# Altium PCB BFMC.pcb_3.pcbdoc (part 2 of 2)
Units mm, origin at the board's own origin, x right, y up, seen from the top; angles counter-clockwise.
Board outline 133.24 x 103.12 mm, 2 copper layers (Top Layer, Bottom Layer); 130 components, 62 nets, 361 pads, 103 vias.
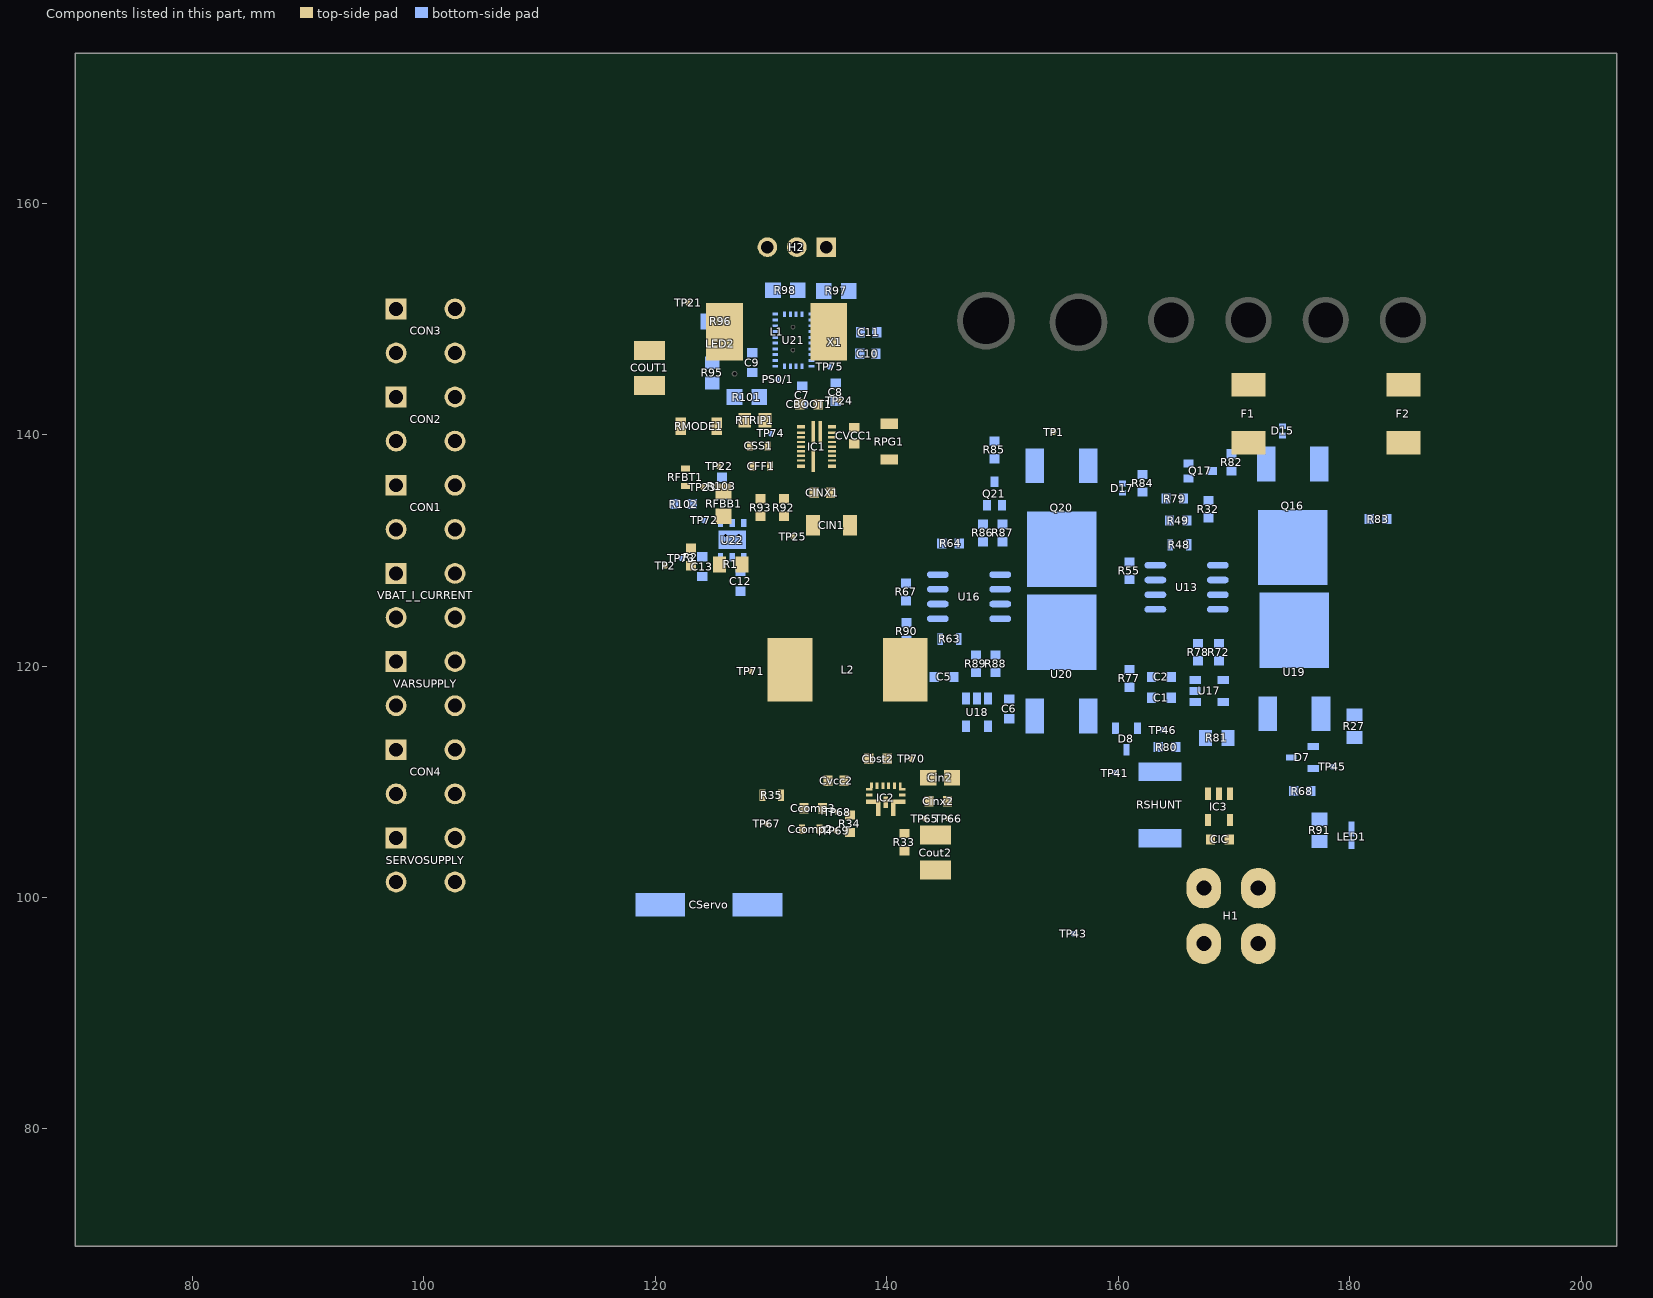
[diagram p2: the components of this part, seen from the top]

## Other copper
Top Layer:
  region net ISHUNT: 170.514,109.198 170.514,108.698 ccw(c170.514,107.877) 169.912,108.435 169.912,109.505 ccw(c170.514,109.941)
  region net UBATT: 166.73,108.725 166.73,109.225 ccw(c166.73,110.37) 167.48,109.505 167.48,108.435 ccw(c166.73,107.61)
  region net OUT_BATT: 166.73,106.445 166.73,106.945 ccw(c166.73,108.06) 167.48,107.235 167.48,106.165 ccw(c166.73,105.3)
  region net +5V: 169.896,105.415 169.396,105.415 ccw(c151.798,105.415) 169.38,106.165 169.912,106.165 ccw(c187.494,105.415)
  region net ADC1: 120.437,128.405 120.674,128.905 120.849,128.912 120.612,128.604 120.609,128.611 120.603,128.611 120.587,128.596 120.541,128.525 120.486,128.444 120.46,128.416 120.448,128.408
  region net ADC1: 121.037,128.905 121.274,128.405 121.263,128.408 121.251,128.416 121.225,128.444 121.17,128.525 121.124,128.596 121.108,128.611 121.102,128.611 121.099,128.604 120.862,128.912
  region net VOUT1: 140.707,106.797 140.407,106.797 ccw(c139.843,106.797) 140.357,107.029 140.757,107.029 ccw(c141.27,106.797)
  region: 139.384,106.648 139.13,106.648 ccw(c138.099,106.648) 139.057,107.029 139.457,107.029 ccw(c140.414,106.648)
  region net +5V: 141.482,108.854 141.182,108.854 ccw(c140.636,108.854) 141.032,109.229 141.607,109.229 ccw(c142.105,108.854)
  region net +5V: 141.182,109.342 141.482,109.342 ccw(c142.071,109.342) 141.607,108.979 141.057,108.979 ccw(c140.592,109.342)
  region net VOUT1: 141.973,108.406 141.973,108.152 ccw(c141.973,107.198) 141.607,108.079 141.607,108.479 ccw(c141.973,109.36)
  region net SW_1: 139.757,108.979 140.057,108.979 ccw(c140.707,108.979) 140.107,108.729 139.707,108.729 ccw(c139.107,108.979)
  region: 138.11,108.152 138.11,108.406 ccw(c138.11,108.506) 138.207,108.479 138.207,108.079 ccw(c138.11,108.052)
  region: 139.152,108.86 139.406,108.86 ccw(c140.88,108.86) 139.457,108.479 138.962,108.479 ccw(c138.676,108.86)
  region net FB_1: 137.756,109.229 137.756,109.529 ccw(c138.206,111.529) 138.206,109.479 138.206,109.229
  region net FB_1: 129.864,106.15 129.364,105.969 129.367,105.981 129.374,105.993 129.398,106.019 129.469,106.07 129.504,106.093 129.53,106.114 129.541,106.131 129.539,106.138 129.532,106.144 129.883,106.325 129.87,106.238
  region net COMP: 135.373,107.5 135.581,107.717 135.615,107.682 135.649,107.651 135.686,107.629 135.707,107.623 135.731,107.62 135.472,107.352 135.468,107.375 135.461,107.397 135.439,107.433 135.408,107.466
  region net COMP: 136.059,107.238 135.847,107.026 135.815,107.059 135.782,107.089 135.746,107.11 135.726,107.117 135.703,107.121 135.971,107.38 135.98,107.338 136,107.302 136.028,107.27
  region net $3N2936: 136.02,105.776 135.963,105.476 135.907,105.478 135.863,105.485 135.795,105.505 135.764,105.514 135.728,105.521 135.684,105.523 135.629,105.52 135.845,105.813 135.854,105.788 135.867,105.772 135.885,105.765 135.907,105.763 135.96,105.77
  region net $3N2936: 135.178,105.765 135.323,106.065 135.366,106.063 135.399,106.056 135.45,106.036 135.474,106.027 135.501,106.019 135.534,106.015 135.576,106.017 135.353,105.728 135.345,105.753 135.332,105.769 135.314,105.776 135.292,105.778 135.239,105.771
  region net OUT_BATT: 133.475,139.113 133.775,139.113 133.775,138.663 133.475,138.663
  region: 135.425,139.763 135.125,139.763 ccw(c134.8,139.763) 134.925,140.063 135.625,140.063 ccw(c135.75,139.763)
  region: 135.425,139.363 135.125,139.363 ccw(c134.8,139.363) 134.925,139.663 135.625,139.663 ccw(c135.75,139.363)
  region: 135.125,140.163 135.425,140.163 ccw(c135.75,140.163) 135.625,139.863 134.925,139.863 ccw(c134.8,140.163)
  region: 135.425,138.963 135.125,138.963 ccw(c134.8,138.963) 134.925,139.263 135.625,139.263 ccw(c135.75,138.963)
  region: 135.125,139.763 135.425,139.763 ccw(c135.75,139.763) 135.625,139.463 134.925,139.463 ccw(c134.8,139.763)
  region: 135.425,138.563 135.125,138.563 ccw(c134.8,138.563) 134.925,138.863 135.625,138.863 ccw(c135.75,138.563)
  region: 135.125,139.363 135.425,139.363 ccw(c135.75,139.363) 135.625,139.063 134.925,139.063 ccw(c134.8,139.363)
  region: 135.425,138.163 135.125,138.163 ccw(c134.8,138.163) 134.925,138.463 135.625,138.463 ccw(c135.75,138.163)
  region: 135.125,138.963 135.425,138.963 ccw(c135.75,138.963) 135.625,138.663 134.925,138.663 ccw(c134.8,138.963)
  region: 135.425,137.763 135.125,137.763 ccw(c134.8,137.763) 134.925,138.063 135.625,138.063 ccw(c135.75,137.763)
  region: 135.125,138.563 135.425,138.563 ccw(c135.75,138.563) 135.625,138.263 134.925,138.263 ccw(c134.8,138.563)
  region: 135.425,137.263 135.125,137.263 ccw(c134.625,137.263) 134.925,137.663 135.625,137.663 ccw(c135.925,137.263)
  region: 135.125,138.163 135.425,138.163 ccw(c135.75,138.163) 135.625,137.863 134.925,137.863 ccw(c134.8,138.163)
  region: 136.006,137.39 136.006,137.136 ccw(c136.006,133.969) 135.625,137.113 135.625,137.413 ccw(c136.006,140.557)
  region: 135.125,137.763 135.425,137.763 ccw(c135.831,137.763) 135.625,137.413 134.925,137.413 ccw(c134.718,137.763)
  region net SW: 134.098,141.544 134.352,141.544 ccw(c137.519,141.544) 134.375,141.163 134.075,141.163 ccw(c130.93,141.544)
  region net FB: 124.424,135.569 124.424,135.369 124.376,135.361 124.331,135.342 124.288,135.314 124.249,135.283 124.249,135.655 124.288,135.624 124.331,135.596 124.376,135.576
  region net FB: 123.741,135.369 123.741,135.569 123.789,135.576 123.835,135.596 123.877,135.624 123.916,135.655 123.916,135.283 123.877,135.314 123.835,135.342 123.789,135.361
  region net EN: 130.287,134.326 130.287,134.58 ccw(c130.287,135.057) 130.668,134.771 130.668,134.136 ccw(c130.287,133.85)
  region net EN: 129,135 129.2,135 ccw(c129.35,135.007) 129.35,134.857 128.85,134.857 ccw(c128.85,135.007)
  region net EN: 129.913,134.58 129.913,134.326 ccw(c129.913,133.85) 129.532,134.136 129.532,134.771 ccw(c129.913,135.057)
  region net +5V: 142.484,110.227 142.484,110.481 ccw(c142.484,110.957) 142.865,110.672 142.865,110.037 ccw(c142.484,109.751)
  region net VCCBOOST: 137.156,110.229 137.156,109.929 ccw(c137.156,109.367) 136.706,109.704 136.706,110.454 ccw(c137.156,110.792)
  region net VOUT1: 146.125,105.896 146.125,104.896 ccw(c146.125,104.228) 145.557,104.579 145.557,106.214 ccw(c146.125,106.564)
  region net VOUT1: 141.357,106.078 141.657,106.078 ccw(c141.882,106.184) 141.882,105.936 141.132,105.936 ccw(c141.132,106.184)
  region net FB_1: 140.325,103.776 140.325,104.276 ccw(c140.325,106.188) 141.075,104.429 141.075,103.622 ccw(c140.325,101.864)
  region net COMP: 135.953,106.982 135.953,107.282 ccw(c135.953,107.789) 136.375,107.507 136.375,106.757 ccw(c135.953,106.475)
  region net COMP: 136.724,107.917 136.978,107.917 ccw(c137.454,107.917) 137.168,107.536 136.533,107.536 ccw(c136.247,107.917)
  region net $3N2936: 135.925,105.476 135.925,105.776 ccw(c135.925,106.338) 136.375,106.001 136.375,105.251 ccw(c135.925,104.913)
  region net VCC: 136.3,140.513 136.3,140.813 ccw(c136.3,141.448) 136.75,141 136.75,140.288 ccw(c136.3,139.95)
  region net VCC: 138.143,140.85 138.143,140.35 ccw(c138.143,139.464) 137.65,140.2 137.65,141 ccw(c138.143,141.736)
  region net OUT_BATT: 133.475,135.861 133.775,135.861 ccw(c134.337,135.861) 134,135.411 133.332,135.411 ccw(c132.691,135.861)
  region net OUT_BATT: 128.786,129.035 128.786,128.535 ccw(c128.786,127.597) 128.036,128.16 128.036,129.41 ccw(c128.786,129.972)
  region net ADC1: 124.221,128.405 124.221,128.905 ccw(c124.221,129.843) 124.971,129.28 124.971,128.096 ccw(c124.221,127.34)
  region net +5V: 169.396,106.215 169.896,106.215 ccw(c173.449,106.215) 169.976,105.465 169.176,105.465 ccw(c168.007,106.215)
  region net +5V: 169.906,103.815 169.406,103.815 ccw(c168.068,103.815) 169.176,104.565 169.976,104.565 ccw(c173.957,103.815)
  region net BST: 140.574,112.02 140.567,111.668 ccw(c140.553,111.555) 140.439,111.555 140.439,112.424 ccw(c141.112,112.424)
  region net SW_1: 137.589,111.855 137.589,112.155 ccw(c137.589,112.718) 138.039,112.38 138.039,111.63 ccw(c137.589,111.293)
  region net SW_1: 138.631,111.174 138.377,111.174 ccw(c137.901,111.174) 138.187,111.555 138.822,111.555 ccw(c139.107,111.174)
  region net COMP: 135.286,107.829 135.286,107.529 ccw(c135.286,106.966) 134.836,107.304 134.836,108.054 ccw(c135.286,108.391)
  region net BOOT: 131.736,142.425 131.736,142.725 ccw(c131.736,143.094) 132.076,142.95 132.076,142.2 ccw(c131.736,142.056)
  region net FB: 123.3,135.569 123.3,135.369 ccw(c123.3,134.483) 123,135.317 123,135.719 ccw(c123.3,135.944)
  region net FB: 126.888,135.2 126.888,135 ccw(c126.888,134.625) 126.588,134.85 126.588,135.35 ccw(c126.888,135.575)
  region net FB: 124.911,135.369 124.911,135.569 ccw(c124.911,135.944) 125.211,135.719 125.211,135.219 ccw(c124.911,134.994)
  region net MODE: 126.056,140.815 126.056,140.615 ccw(c126.056,140.24) 125.756,140.465 125.756,140.965 ccw(c126.056,141.19)
  region net PGOOD: 140.35,136.95 140.05,136.95 ccw(c139.487,136.95) 139.825,137.4 140.575,137.4 ccw(c140.912,136.95)
  region net VCC: 138.7,140.838 138.7,141.338 ccw(c138.7,145.921) 139.45,141.4 139.45,140.5 ccw(c138.7,139.837)
  region net TRIP: 130.207,141.349 130.207,141.149 ccw(c130.207,140.965) 130.026,140.999 130.026,141.499 ccw(c130.207,141.533)
  region net FB: 130.441,137.364 130.441,137.164 ccw(c130.441,136.789) 130.141,137.014 130.141,137.514 ccw(c130.441,137.739)
  region net FB: 129.991,136.564 129.791,136.564 ccw(c129.416,136.564) 129.641,136.864 130.141,136.864 ccw(c130.366,136.564)
  region net SS_REFIN: 130.236,139.063 130.236,138.863 ccw(c130.236,138.488) 129.936,138.713 129.936,139.213 ccw(c130.236,139.438)
  region net $3N2936: 134.877,106.065 134.877,105.765 ccw(c134.877,105.203) 134.427,105.54 134.427,106.29 ccw(c134.877,106.628)
  region net FB_1: 131.556,109.005 131.556,108.705 ccw(c131.556,108.143) 131.106,108.48 131.106,109.23 ccw(c131.556,109.568)
  region net VBATT1: 165.656,97.399 165.905,97.857 165.992,97.776 166.085,97.703 166.184,97.641 166.234,97.614 166.286,97.592 166.338,97.574 166.391,97.56 166.444,97.552 166.497,97.549 166.551,97.551 166.604,97.561 166.657,97.577 166.709,97.6 165.936,96.618 165.945,96.667 165.949,96.718 165.949,96.77 165.945,96.823 165.924,96.929 165.89,97.035 165.844,97.137 165.788,97.234 165.725,97.322
  region net OUT_BATT2: 171.694,103.383 172.494,103.383 172.497,103.306 172.507,103.227 172.523,103.146 172.545,103.063 172.572,102.98 172.604,102.897 172.641,102.814 172.681,102.733 172.772,102.574 172.873,102.427 172.927,102.359 172.982,102.295 173.037,102.236 173.094,102.183 171.094,102.183 171.15,102.236 171.205,102.295 171.26,102.359 171.314,102.427 171.415,102.574 171.506,102.733 171.546,102.814 171.583,102.897 171.615,102.98 171.642,103.063 171.664,103.146 171.68,103.227 171.69,103.306
  region: 131.047,138.513 131.189,138.372 131.16,138.333 131.142,138.286 131.131,138.237 131.126,138.187 130.863,138.451 130.912,138.455 130.962,138.466 131.008,138.485
  region: 131.28,140.935 131.054,140.878 130.962,140.964 130.912,141.006 130.863,141.042 131.219,141.121 131.208,141.097 131.204,141.072 131.207,141.048 131.214,141.024 131.242,140.977
  region net PGOOD: 131.743,136.636 132.043,136.647 132.042,136.598 132.045,136.552 132.056,136.51 132.066,136.491 132.081,136.472 131.709,136.461 131.723,136.481 131.732,136.501 131.742,136.543 131.743,136.588
  region net PGOOD: 139.735,136.648 139.947,136.435 139.912,136.401 139.882,136.368 139.859,136.331 139.852,136.31 139.849,136.286 139.586,136.55 139.609,136.553 139.631,136.56 139.668,136.582 139.701,136.613
  region net +5V: 142.027,109.592 ccw(c141.205,109.592) 141.727,110.227 142.177,110.354 142.627,110.227 ccw(c143.149,109.592) 142.327,109.592
Bottom Layer:
  region net $1N1798: 177.715,113.3 177.715,112.8 ccw(c177.715,111.388) 177.325,112.745 177.325,113.355 ccw(c177.715,114.712)
  region net $1N1798: 176.587,113.636 177.087,113.636 ccw(c177.372,113.636) 177.325,113.355 176.349,113.355 ccw(c176.301,113.636)
  region net UBATT: 173.725,111.85 173.725,112.35 ccw(c173.725,137.1) 174.475,112.361 174.475,111.839 ccw(c173.725,87.1)
  region net $1N1788: 159.45,115.401 160.05,115.401 ccw(c167.811,115.401) 160.055,115.125 159.445,115.125 ccw(c151.688,115.401)
  region net $1N1788: 159.95,113.841 159.55,113.841 ccw(c159.045,113.841) 159.445,114.15 160.055,114.15 ccw(c160.455,113.841)
  region net UBATT: 160.95,111.525 160.45,111.525 ccw(c135.7,111.525) 160.438,112.275 160.961,112.275 ccw(c185.7,111.525)
  region net UBATT: 161.711,113.013 161.711,112.513 ccw(c161.711,111.21) 160.961,112.275 160.961,113.25 ccw(c161.711,114.315)
  region net $1N2516: 166.314,135.544 165.814,135.544 ccw(c165.48,135.544) 165.614,135.85 166.514,135.85 ccw(c166.647,135.544)
  region net $1N2412: 169.296,137.11 169.296,136.61 ccw(c169.296,133.747) 168.546,136.51 168.546,137.21 ccw(c169.296,139.972)
  region net $1N20962: 166.88,132.81 166.88,132.31 ccw(c166.88,131.408) 166.336,132.128 166.336,132.992 ccw(c166.88,133.712)
  region net $1N20946: 164.576,131.893 164.276,131.893 ccw(c164.042,131.893) 164.051,132.128 164.801,132.128 ccw(c164.811,131.893)
  region net $1N20674: 161.206,126.328 160.706,126.328 ccw(c159.07,126.328) 160.524,127.078 161.388,127.078 ccw(c162.842,126.328)
  region net $1N20674: 162.138,127.685 162.138,127.185 ccw(c162.138,124.49) 161.388,127.078 161.388,127.885 ccw(c162.138,129.191)
  region net $1N27792: 154.086,137.564 154.086,137.064 ccw(c154.086,136.562) 153.6,136.689 153.6,137.939 ccw(c154.086,138.065)
  region net $1N27792: 152.55,139.564 153.05,139.564 ccw(c153.988,139.564) 153.425,138.814 152.175,138.814 ccw(c151.613,139.564)
  region net $1N27799: 150.25,132.684 149.75,132.684 ccw(c147.665,132.684) 149.61,133.434 150.31,133.434 ccw(c154.936,132.684)
  region net $1N27793: 149.05,137.116 149.55,137.116 ccw(c152.412,137.116) 149.65,136.366 148.95,136.366 ccw(c146.187,137.116)
  region net $1N27811: 147.406,130.85 147.406,130.35 ccw(c147.406,128.714) 146.656,130.168 146.656,131.032 ccw(c147.406,132.486)
  region net $1N27807: 144.996,129.625 144.496,129.625 ccw(c143.457,129.625) 144.343,130.168 145.149,130.168 ccw(c146.035,129.625)
  region net $1N27792: 159.296,134.66 159.296,135.16 ccw(c159.296,139.727) 160.046,135.222 160.046,134.722 ccw(c160.046,130.155)
  region net $1N27792: 161.396,135.16 161.396,134.66 ccw(c160.646,130.155) 160.646,134.722 160.646,135.222 ccw(c161.396,139.727)
  region net $1N27822: 141.95,124.493 141.45,124.493 ccw(c139.999,124.493) 141.241,125.243 142.105,125.243 ccw(c143.842,124.493)
  region net $1N27822: 142.318,125.897 142.318,125.397 ccw(c142.318,125.171) 142.105,125.243 142.105,126.05 ccw(c142.318,126.122)
  region net VBATT1: 161.206,117.028 160.706,117.028 ccw(c159.07,117.028) 160.524,117.778 161.388,117.778 ccw(c162.842,117.028)
  region net $1N20674: 160.706,120.842 161.206,120.842 ccw(c162.842,120.842) 161.388,120.092 160.524,120.092 ccw(c159.07,120.842)
  region net +VCC2: 167.089,119.293 166.589,119.293 ccw(c164.211,119.293) 166.468,120.043 167.332,120.043 ccw(c168.369,119.293)
  region net +VCC2: 165.934,120.136 165.934,120.636 ccw(c165.934,121.41) 166.468,120.85 166.468,120.043 ccw(c165.934,118.549)
  region net $1N21052: 168.082,122.203 168.082,121.703 ccw(c168.082,119.791) 167.332,121.55 167.332,122.357 ccw(c168.082,124.115)
  region net $1N21052: 167.518,121.703 167.518,122.203 ccw(c167.518,124.115) 168.268,122.357 168.268,121.55 ccw(c167.518,119.791)
  region net $1N21052: 169.734,122.203 169.734,121.703 ccw(c169.734,120.442) 169.132,121.55 169.132,122.357 ccw(c169.734,123.464)
  region net $1N2516: 166.786,134.71 166.786,134.21 ccw(c166.786,132.574) 166.036,134.028 166.036,134.892 ccw(c166.786,136.346)
  region net $1N2516: 165.383,135.113 165.883,135.113 ccw(c166.119,135.113) 166.036,134.892 165.23,134.892 ccw(c165.146,135.113)
  region net UBATT: 175.396,108.018 174.896,108.018 ccw(c172.984,108.018) 174.743,108.768 175.549,108.768 ccw(c177.308,108.018)
  region net UBATT: 173.993,108.95 173.993,109.45 ccw(c173.993,111.086) 174.743,109.632 174.743,108.768 ccw(c173.993,107.314)
  region net $1N1798: 177.806,109.45 177.806,108.95 ccw(c177.806,107.314) 177.056,108.768 177.056,109.632 ccw(c177.806,111.086)
  region net UBATT: 162.358,112.75 162.358,113.25 ccw(c162.358,114.632) 163.043,113.432 163.043,112.568 ccw(c162.358,111.368)
  region net $1N1788: 165.787,113.25 165.787,112.75 ccw(c165.787,112.15) 165.356,112.568 165.356,113.432 ccw(c165.787,113.85)
  region net $1N1788: 164.753,113.918 165.153,113.918 ccw(c165.836,113.918) 165.356,113.432 164.55,113.432 ccw(c164.07,113.918)
  region net $1N1798: 178.511,115.473 178.511,116.273 ccw(c178.511,128.344) 179.711,116.332 179.711,115.2 ccw(c178.511,112.696)
  region net $1N1788: 166.587,113.55 166.587,114.05 ccw(c166.587,114.43) 166.967,114.425 166.967,113.175 ccw(c166.587,113.169)
  region net $1N2337: 170.979,138.605 170.979,138.105 ccw(c170.979,136.193) 170.229,137.952 170.229,138.759 ccw(c170.979,140.517)
  region net $1N2412: 168.615,136.61 168.615,137.11 ccw(c168.615,139.164) 169.365,137.252 169.365,136.445 ccw(c168.615,134.819)
  region net $1N27792: 149.047,140.079 149.547,140.079 ccw(c149.807,140.079) 149.729,139.831 148.865,139.831 ccw(c148.786,140.079)
  region net $1N27793: 149.55,136.767 149.05,136.767 ccw(c147.437,136.767) 148.865,137.517 149.729,137.517 ccw(c151.21,136.767)
  region net $1N27799: 148.818,132.003 148.818,132.503 ccw(c148.818,134.415) 149.568,132.657 149.568,131.85 ccw(c148.818,130.091)
  region net $1N27799: 149.75,133.407 150.25,133.407 ccw(c151.886,133.407) 150.432,132.657 149.568,132.657 ccw(c148.113,133.407)
  region net $1N32332: 148.808,119.826 149.049,120.009 ccw(c149.527,120.645) 149.527,119.85 148.968,119.348 ccw(c148.172,119.348)
  region net +VCC3: 150.186,121.171 150.186,120.871 ccw(c150.186,120.48) 149.832,120.646 149.832,121.357 ccw(c150.186,121.601)
  region net +VCC3: 149.15,122.013 149.65,122.013 ccw(c150.924,122.013) 149.832,121.357 148.968,121.357 ccw(c147.875,122.013)
  region net $1N32332: 147.75,122.107 148.25,122.107 ccw(c150.574,121.357) 148.132,121.357 147.375,121.357 ccw(c146.812,122.107)
  region net $1N32332: 148.291,120.768 148.243,120.391 ccw(c147.766,119.755) 147.766,120.55 148.132,121.245 ccw(c148.927,121.245)
  region net $1N27822: 141.45,124.907 141.95,124.907 ccw(c143.586,124.907) 142.132,124.157 141.268,124.157 ccw(c139.813,124.907)
  region net VBATT2: 142.1,120.643 141.3,120.643 ccw(c118.785,120.643) 141.268,121.843 142.132,121.843 ccw(c164.614,120.643)
  region net VBATT2: 142.582,122.397 142.582,122.097 ccw(c142.582,121.534) 142.132,121.872 142.132,122.622 ccw(c142.582,122.959)
  region net ISHUNT: 155.804,96.888 156.046,97.353 156.053,97.343 156.057,97.329 156.058,97.294 156.045,97.21 156.037,97.171 156.034,97.139 156.039,97.119 156.046,97.115 156.056,97.116 155.911,96.748 155.861,96.821
  region net ISHUNT: 156.603,96.796 156.138,96.554 156.071,96.611 155.998,96.661 156.366,96.806 156.365,96.796 156.369,96.789 156.389,96.784 156.421,96.787 156.46,96.795 156.544,96.808 156.579,96.807 156.593,96.803
  region net $1N1788: 163.503,114.297 163.503,114.697 163.601,114.703 163.677,114.715 163.753,114.725 163.797,114.726 163.85,114.723 163.803,114.225 163.753,114.232 163.713,114.242 163.653,114.267 163.625,114.278 163.594,114.288 163.554,114.295
  region net $1N1788: 164.127,114.674 164.127,114.274 164.072,114.272 164.02,114.266 163.93,114.249 163.863,114.232 163.827,114.224 163.827,114.724 163.863,114.716 163.93,114.699 164.02,114.682 164.072,114.676
  region net VBATT1: 165.883,117.605 165.883,118.105 ccw(c165.883,118.528) 166.156,118.205 166.156,117.505 ccw(c165.883,117.183)
  region net +VCC2: 165.646,118.555 165.646,119.055 ccw(c165.646,120.405) 166.156,119.155 166.156,118.455 ccw(c165.646,117.205)
  region net +VCC2: 166.589,119.905 167.089,119.905 ccw(c171.323,119.905) 167.156,119.155 166.214,119.155 ccw(c165.651,119.905)
  region net VBATT2: 147.65,117.7 147.95,117.7 ccw(c148.15,4069.125) 148.15,117.7 147.45,117.7 ccw(c147.449,4069.125)
  region net +VCC3: 149.55,117.35 149.55,117.05 ccw(c149.55,116.487) 149.1,116.825 149.1,117.575 ccw(c149.55,117.912)
  region net UBATT: 175.961,106.55 175.961,107.05 ccw(c175.961,108.187) 176.711,107.332 176.711,106.2 ccw(c175.961,105.571)
  region net $1N40141: 178.838,104.845 178.838,104.345 ccw(c178.838,100.686) 178.088,104.267 178.088,105.22 ccw(c178.838,105.783)
  region net $1N20931: 162.951,125.932 163.451,125.932 163.451,125.792 163.456,125.657 163.47,125.53 163.482,125.471 163.497,125.416 163.517,125.366 163.542,125.32 163.572,125.28 163.609,125.246 163.652,125.219 163.702,125.199 163.76,125.186 163.826,125.182 162.576,125.182 162.642,125.186 162.699,125.199 162.749,125.219 162.792,125.246 162.829,125.28 162.859,125.32 162.884,125.366 162.904,125.416 162.919,125.471 162.931,125.53 162.945,125.657 162.95,125.792
  region net $1N20931: 163.451,125.128 162.951,125.128 162.95,125.268 162.945,125.403 162.931,125.53 162.919,125.589 162.904,125.644 162.884,125.694 162.859,125.739 162.829,125.78 162.792,125.813 162.749,125.841 162.699,125.861 162.642,125.874 162.576,125.878 163.826,125.878 163.76,125.874 163.702,125.861 163.652,125.841 163.609,125.813 163.572,125.78 163.542,125.739 163.517,125.694 163.497,125.644 163.482,125.589 163.47,125.53 163.456,125.403 163.451,125.268
  region net $1N20931: 164.308,126.315 164.308,126.015 164.225,126.009 164.146,125.994 164.073,125.972 164.008,125.946 163.907,125.899 163.858,125.878 163.858,126.452 163.907,126.431 164.008,126.383 164.073,126.358 164.146,126.336 164.225,126.321
  region net $1N20674: 161.794,127.185 161.794,127.685 162.065,127.691 162.3,127.703 162.544,127.722 162.544,127.148 162.3,127.166 162.065,127.179
  region net +VCC2: 167.192,124.645 167.192,125.145 167.463,125.151 167.698,125.163 167.942,125.182 167.942,124.608 167.698,124.626 167.463,124.639
  region net $1N20962: 167.492,126.015 167.492,126.315 167.574,126.321 167.653,126.336 167.726,126.358 167.791,126.383 167.892,126.431 167.942,126.452 167.942,125.878 167.892,125.899 167.791,125.946 167.726,125.972 167.653,125.994 167.574,126.009
  region net $1N21052: 169.756,127.685 169.756,127.185 169.576,127.179 169.421,127.166 169.256,127.148 169.256,127.722 169.421,127.703 169.576,127.691
  region net $1N20946: 167.492,128.555 167.492,128.855 167.574,128.861 167.653,128.876 167.726,128.898 167.791,128.923 167.892,128.971 167.942,128.992 167.942,128.418 167.892,128.439 167.791,128.486 167.726,128.512 167.653,128.534 167.574,128.549
  region net $1N27802: 144.151,125.132 144.651,125.132 144.651,124.992 144.656,124.857 144.67,124.73 144.682,124.671 144.697,124.616 144.717,124.566 144.742,124.52 144.772,124.48 144.809,124.446 144.852,124.419 144.902,124.399 144.96,124.386 145.026,124.382 143.776,124.382 143.842,124.386 143.899,124.399 143.949,124.419 143.992,124.446 144.029,124.48 144.059,124.52 144.084,124.566 144.104,124.616 144.119,124.671 144.131,124.73 144.145,124.857 144.15,124.992
  region net $1N27802: 144.87,123.058 144.37,123.058 144.369,123.198 144.364,123.333 144.35,123.46 144.338,123.519 144.323,123.574 144.303,123.624 144.278,123.669 144.248,123.71 144.212,123.743 144.169,123.771 144.119,123.791 144.061,123.804 143.995,123.808 145.058,123.808 144.994,123.804 144.942,123.791 144.901,123.771 144.87,123.743 144.848,123.71 144.833,123.669 144.825,123.624 144.823,123.574 144.83,123.46 144.846,123.333 144.863,123.198
  region net $1N27802: 144.651,124.328 144.151,124.328 144.15,124.468 144.145,124.603 144.131,124.73 144.119,124.789 144.104,124.844 144.084,124.894 144.059,124.939 144.029,124.98 143.992,125.013 143.949,125.041 143.899,125.061 143.842,125.074 143.776,125.078 145.026,125.078 144.96,125.074 144.902,125.061 144.852,125.041 144.809,125.013 144.772,124.98 144.742,124.939 144.717,124.894 144.697,124.844 144.682,124.789 144.67,124.73 144.656,124.603 144.651,124.468
  region net $1N27822: 143.307,126.385 143.307,126.885 143.463,126.891 143.597,126.903 143.744,126.922 143.744,126.348 143.597,126.366 143.463,126.379
  region net +VCC3: 150.948,124.319 150.948,123.819 150.823,123.815 150.688,123.809 150.554,123.805 150.43,123.809 150.482,124.381 150.602,124.365 150.714,124.344 150.827,124.326 150.886,124.321
  region net $1N27811: 150.974,125.615 150.974,125.115 150.787,125.109 150.627,125.096 150.456,125.078 150.456,125.652 150.627,125.633 150.787,125.621
  region net $1N32332: 148.392,126.385 148.392,126.885 148.663,126.891 148.898,126.903 149.142,126.922 149.142,126.348 148.898,126.366 148.663,126.379
  region net $1N27807: 148.392,127.655 148.392,128.155 148.663,128.161 148.898,128.173 149.142,128.192 149.142,127.618 148.898,127.636 148.663,127.649
  region net $1N2516: 166.598,134.21 166.598,134.71 ccw(c166.598,177.317) 167.348,134.717 167.348,133.91 ccw(c166.598,133.122)
  region net $1N20962: 168.662,132.957 168.662,132.657 ccw(c168.662,132.094) 168.212,132.432 168.212,133.182 ccw(c168.662,133.519)
  region net $1N20962: 167.126,132.557 167.126,133.057 ccw(c167.126,133.293) 167.348,133.21 167.348,132.403 ccw(c167.126,132.32)
  region net $1N27811: 147.118,130.35 147.118,130.85 ccw(c147.118,131.938) 147.868,131.15 147.868,130.343 ccw(c147.118,87.742)
  region net $1N27811: 148.61,129.8 148.11,129.8 ccw(c147.379,129.8) 147.868,130.343 148.732,130.343 ccw(c149.884,129.8)
  region net $1N27799: 149.482,132.503 149.482,132.003 ccw(c149.482,130.091) 148.732,131.85 148.732,132.657 ccw(c149.482,134.415)
  region net $1N1798: 177.464,114.013 176.964,114.013 ccw(c176.58,114.013) 176.714,114.373 177.839,114.373 ccw(c177.839,113.997)
  region net $1N1798: 179.514,116.273 179.514,115.473 ccw(c179.514,113.973) 178.314,114.873 178.314,116.873 ccw(c179.514,117.773)
  region net $1N1788: 159.099,116.115 159.099,115.515 ccw(c159.099,114.39) 158.199,115.065 158.199,116.565 ccw(c159.099,117.24)
  region net $1N2337: 174.201,138.01 174.201,137.51 ccw(c174.201,136.804) 173.578,137.135 173.578,138.385 ccw(c174.201,138.715)
  region net $1N2337: 171.228,138.105 171.228,138.605 ccw(c171.228,139.572) 171.978,138.962 171.978,137.73 ccw(c171.228,137.168)
  region net $1N2337: 172.55,139.479 173.05,139.479 ccw(c173.595,139.479) 173.425,138.962 172.175,138.962 ccw(c172.006,139.479)
  region net UBATT: 163.85,109.639 163.35,109.639 ccw(c162.909,109.639) 162.975,110.075 164.225,110.075 ccw(c164.291,109.639)
  region net OUT_BATT: 163.35,106.114 163.85,106.114 ccw(c164.225,106.391) 164.225,105.925 162.975,105.925 ccw(c162.975,106.391)
  region net +3V3: 132.266,145.355 132.066,145.355 ccw(c130.254,145.355) 132.041,145.655 132.291,145.655 ccw(c134.078,145.355)
  region net $5N2144: 131.766,145.355 131.566,145.355 ccw(c129.754,145.355) 131.541,145.655 131.791,145.655 ccw(c133.578,145.355)
  region net $5N394: 129.803,147.305 129.803,147.505 ccw(c129.803,149.317) 130.103,147.53 130.103,147.28 ccw(c129.803,145.493)
  region net $5N968: 129.803,147.805 129.803,148.005 ccw(c129.803,149.817) 130.103,148.03 130.103,147.78 ccw(c129.803,145.993)
  region net GPIO6: 129.803,148.305 129.803,148.505 ccw(c129.803,150.317) 130.103,148.53 130.103,148.28 ccw(c129.803,146.493)
  region net +3V3: 131.566,150.865 131.766,150.865 ccw(c132.658,150.865) 131.791,150.655 131.541,150.655 ccw(c130.674,150.865)
  region net SCK/SCL: 132.566,150.955 132.766,150.955 ccw(c134.578,150.955) 132.791,150.655 132.541,150.655 ccw(c130.754,150.955)
  region net SDI/SDA: 134.029,150.505 134.029,150.305 ccw(c134.029,148.493) 133.729,150.28 133.729,150.53 ccw(c134.029,152.317)
  region: 132.936,147.815 132.936,148.015 ccw(c132.936,150.847) 133.229,148.03 133.229,147.78 ccw(c132.936,146.565)
  region net SDI/SDA: 134.98,154.595 134.48,154.595 ccw(c133.542,154.595) 134.105,155.345 135.355,155.345 ccw(c135.917,154.595)
  region net SCK/SCL: 132.466,155.033 131.966,155.033 131.964,155.085 131.957,155.133 131.947,155.177 131.933,155.218 131.916,155.256 131.895,155.291 131.846,155.358 131.788,155.422 131.723,155.485 131.654,155.553 131.582,155.628 132.849,155.628 132.778,155.553 132.709,155.485 132.644,155.422 132.586,155.358 132.537,155.291 132.516,155.256 132.499,155.218 132.485,155.177 132.475,155.133 132.468,155.085
  region net GPIO6: 129.946,154.86 129.446,154.86 129.444,154.913 129.437,154.966 129.427,155.018 129.412,155.069 129.374,155.169 129.324,155.266 129.265,155.359 129.199,155.448 129.129,155.533 129.056,155.614 130.323,155.643 130.252,155.558 130.184,155.469 130.121,155.375 130.064,155.278 130.015,155.177 129.978,155.074 129.954,154.968 129.948,154.914
  region net XOUT32: 136.391,148.747 136.391,148.493 ccw(c136.391,148.016) 136.01,148.302 136.01,148.937 ccw(c136.391,149.223)
  region net XOUT32: 134.64,148.493 134.64,148.747 ccw(c134.64,149.094) 134.95,148.937 134.95,148.302 ccw(c134.64,148.145)
  region net XIN32: 134.58,147.173 134.58,147.427 ccw(c134.58,147.881) 134.95,147.617 134.95,146.982 ccw(c134.58,146.718)
  region net XIN32: 136.391,147.427 136.391,147.173 ccw(c136.391,146.697) 136.01,146.982 136.01,147.617 ccw(c136.391,147.903)
  region net XIN32: 136.879,147.173 136.879,147.427 ccw(c136.879,150.626) 137.26,147.45 137.26,146.982 ccw(c136.879,146.697)
  region net XOUT32: 136.939,148.493 136.939,148.747 ccw(c136.939,149.223) 137.32,148.937 137.32,148.41 ccw(c136.939,147.577)
  region net +3V3: 123.161,149.525 123.161,150.025 ccw(c123.161,150.963) 123.911,150.4 123.911,149.15 ccw(c123.161,148.588)
  region net GPIO6: 127.711,149.875 127.711,149.675 ccw(c127.711,149.3) 127.411,149.525 127.411,150.025 ccw(c127.711,150.25)
  region net GPIO6: 126.486,151.214 126.986,151.214 ccw(c127.923,151.214) 127.361,150.464 126.111,150.464 ccw(c125.548,151.214)
  region net SDI/SDA: 134.836,151.427 134.636,151.427 ccw(c134.261,151.427) 134.486,151.727 134.986,151.727 ccw(c135.211,151.427)
  region net SDI/SDA: 134.48,153.854 134.98,153.854 ccw(c136.266,153.854) 135.221,153.104 134.105,153.104 ccw(c133.542,153.854)
  region net +3V3: 136.466,153.854 136.966,153.854 ccw(c137.903,153.854) 137.341,153.104 136.091,153.104 ccw(c135.528,153.854)
  region net +3V3: 130.266,151.487 130.066,151.487 ccw(c129.691,151.487) 129.916,151.787 130.416,151.787 ccw(c130.641,151.487)
  region net +3V3: 130.1,153.909 130.6,153.909 ccw(c131.872,153.909) 130.841,153.164 129.725,153.164 ccw(c129.172,153.909)
  region net SCK/SCL: 132.766,151.487 132.566,151.487 ccw(c132.191,151.487) 132.416,151.787 132.916,151.787 ccw(c133.141,151.487)
  region net SCK/SCL: 131.966,153.914 132.466,153.914 ccw(c133.403,153.914) 132.841,153.164 131.641,153.164 ccw(c130.938,153.914)
  region net $5N2144: 129.936,143.335 129.936,143.135 ccw(c129.936,142.808) 129.661,142.985 129.661,143.485 ccw(c129.936,143.662)
  region net +3V3: 127.086,141.797 126.586,141.797 ccw(c125.648,141.797) 126.211,142.547 127.461,142.547 ccw(c128.023,141.797)
  region net +3V3: 125.411,142.985 125.411,143.485 ccw(c125.411,144.423) 126.161,143.86 126.161,142.61 ccw(c125.411,142.048)
  region net +3V3: 133.896,144.445 133.896,143.945 ccw(c133.896,141.995) 133.146,143.795 133.146,144.595 ccw(c133.896,146.395)
  region net +3V3: 131.955,143.945 131.955,144.445 ccw(c131.955,144.802) 132.246,144.595 132.246,143.795 ccw(c131.955,143.588)
  region net +3V3: 132.596,144.895 132.796,144.895 ccw(c133.171,144.895) 132.946,144.595 132.446,144.595 ccw(c132.221,144.895)
  region net +3V3: 134.4,144.21 134.4,144.71 ccw(c134.4,146.66) 135.15,144.86 135.15,144.06 ccw(c134.4,142.26)
  region net +3V3: 135.413,145.241 135.667,145.241 ccw(c136.143,145.241) 135.857,144.86 135.222,144.86 ccw(c134.937,145.241)
  region net $5N968: 126.926,148.005 126.926,147.805 ccw(c126.926,147.43) 126.626,147.655 126.626,148.155 ccw(c126.926,148.38)
  region net $5N959: 125.146,146.709 124.646,146.709 ccw(c120.565,146.709) 124.576,147.459 125.176,147.459 ccw(c134.388,146.709)
  region net $5N959: 124.646,147.512 125.146,147.512 ccw(c126.083,147.512) 125.521,146.762 124.271,146.762 ccw(c123.708,147.512)
  region net +3V3: 125.146,143.241 124.646,143.241 ccw(c123.858,143.241) 124.271,143.912 125.521,143.912 ccw(c125.934,143.241)
  region net VBATT1: 164.866,116.055 164.366,116.055 ccw(c162.79,116.055) 164.176,116.805 164.976,116.805 ccw(c167.476,116.055)
  region net VBATT1: 165.283,117.505 165.283,117.005 ccw(c165.283,116.669) 164.976,116.805 164.976,117.705 ccw(c165.283,117.841)
  region net +VCC2: 165.396,119.305 165.396,118.805 ccw(c165.396,118.264) 164.976,118.605 164.976,119.505 ccw(c165.396,119.846)
  region net VBATT2: 146.124,118.4 145.824,118.4 ccw(c145.599,118.379) 145.599,118.605 146.196,118.605 ccw(c146.452,118.4)
  region net VBATT2: 145.237,119.55 145.547,119.664 ccw(c146.025,120.301) 146.025,119.505 145.396,119.073 ccw(c144.6,119.073)
  region net +VCC3: 150.468,118.005 150.768,118.005 ccw(c151.331,118.005) 150.993,117.555 150.243,117.555 ccw(c149.906,118.005)
  region net +VCC3: 149.676,117.05 149.676,117.35 ccw(c149.676,117.946) 150.126,117.555 150.126,116.825 ccw(c149.676,116.487)
  region net $5N394: 129.126,147.175 129.126,146.975 ccw(c129.126,146.6) 128.826,146.825 128.826,147.325 ccw(c129.126,147.55)
  region net +3V3: 128.556,128.425 128.556,127.925 ccw(c128.556,125.975) 127.806,127.775 127.806,128.575 ccw(c128.556,130.375)
  region net $1N40141: 179.156,104.345 179.156,104.845 ccw(c179.156,106.351) 179.906,105.045 179.906,104.175 ccw(c179.156,102.606)
  region net $1N20946: 166.21,129.55 165.91,129.55 ccw(c164.604,129.55) 165.83,130 166.33,130 ccw(c167.114,129.55)
  region net $1N20946: 165.91,131.34 166.21,131.34 ccw(c166.752,131.34) 166.33,131 165.83,131 ccw(c165.147,131.34)
  region net $1N20931: 164.63,129.55 164.33,129.55 ccw(c163.267,129.55) 164.23,130 164.73,130 ccw(c165.692,129.55) 164.63,129.55
  region net $1N27807: 146.07,123.29 146.37,123.29 ccw(c147.432,123.29) 146.47,122.84 145.97,122.84 ccw(c145.007,123.29)
  region net VBATT2: 164.886,100.415 164.886,101.215 164.969,101.217 165.054,101.224 165.14,101.236 165.227,101.253 165.314,101.274 165.401,101.3 165.486,101.33 165.569,101.365 165.65,101.404 165.727,101.447 165.801,101.495 165.869,101.548 165.933,101.604 165.991,101.665 166.042,101.73 166.086,101.799 166.086,99.83 166.042,99.9 165.991,99.965 165.933,100.025 165.869,100.082 165.801,100.134 165.727,100.182 165.65,100.226 165.569,100.265 165.486,100.3 165.401,100.33 165.314,100.356 165.227,100.377 165.14,100.394 165.054,100.405 164.969,100.413
  region net +3V3: 135.391,145.708 135.212,145.528 135.177,145.557 135.135,145.583 135.089,145.602 135.046,145.61 135.31,145.874 135.318,145.83 135.337,145.785 135.363,145.742
  region net +3V3: 134.729,146.012 134.908,146.191 134.943,146.163 134.985,146.137 135.03,146.118 135.074,146.109 134.81,145.846 134.802,145.889 134.783,145.935 134.757,145.977
  region net PGOOD: 132.241,136.45 132.241,136.15 132.193,136.151 132.147,136.149 132.105,136.138 132.085,136.128 132.066,136.114 132.066,136.486 132.085,136.472 132.105,136.462 132.147,136.451 132.193,136.449
  region net PGOOD: 139.258,136.15 139.258,136.45 139.307,136.449 139.352,136.451 139.394,136.462 139.414,136.472 139.433,136.486 139.433,136.114 139.414,136.128 139.394,136.138 139.352,136.149 139.307,136.151
  region net +3V3: 130.6,153.734 130.1,153.496 130.103,153.507 130.111,153.519 130.139,153.545 130.22,153.6 130.292,153.646 130.307,153.662 130.307,153.668 130.301,153.671 130.606,153.909
  region net +3V3: 123.275,153.73 122.775,153.501 122.778,153.512 122.786,153.524 122.813,153.55 122.891,153.603 122.958,153.649 122.972,153.666 122.971,153.671 122.964,153.676 123.286,153.905 123.28,153.817
  region net $1N27807: 148.73,128.155 cw(c148.73,131.776) 146.169,129.216 145.83,128.847 cw(c143.27,126.286) 146.891,126.286 147.191,126.155 cw(c148.691,126.155) 148.691,127.655
  region net +3V3: 124.646,144.462 cw(c123.442,144.462) 124.146,143.485 124.89,143.235 125.646,143.485 cw(c126.35,144.462) 125.146,144.462
  region net +3V3: 124.586,150.025 cw(c124.586,151.992) 123.275,150.525 123.025,149.759 123.275,149.025 cw(c124.586,147.558) 124.586,149.525

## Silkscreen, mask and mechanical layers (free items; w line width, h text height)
Top Silkscreen Layer:
  text "BFMC POWER BOARD D SAMPLE (FOOTPRINT>0603)" at 108.696,163.575 h3.05
  text "RESET" at 126.42,154.98 h0.7
  text "SDA" at 136.32,154.86 h0.7
  text "SCL" at 131.895,154.455 h0.5
  text "-" at 170.458,154.056 h3.05
  text "+" at 177.12,153.96 h3.05
  text "+" at 163.738,153.936 h3.05
  text "+" at 155.458,153.876 h3.05
  text "-" at 184.078,153.876 h3.05
  text "-" at 147.72,153.78 h3.05
  text "+" at 111.238,149.256 h3.05
  text "-" at 113.724,146.998 h3.05 r90
  text "Engine" at 145.56,142.44 h3.05
  text "+" at 111.36,142.14 h3.05
  text "Bat1" at 176.76,141.96 h3.05
  text "Bat2" at 162.6,141.84 h3.05
  text "-" at 113.906,139.462 h3.05 r90
  text "+" at 111.48,133.98 h3.05
  text "-" at 113.88,131.34 h3.05 r90
  text "Vbat" at 111.24,130.26 h1 r270
  text "I_Current" at 111.48,127.2 h0.8 r270
  text "Def. 12V" at 114.3,121.8 h1.14 r270
  text "+" at 111.058,119.196 h3.05
  text "_" at 111.9,118.2 h3.05 r270
  text "+" at 110.878,111.096 h3.05
  text "-" at 110.256,110.222 h3.05 r270
  text "+" at 111.058,103.716 h3.05
  text "_" at 111.9,102.6 h3.05 r270
  text "BFMC POWER BOARD  V3" at 121.837,96.195 h3.05
Mechanical Layer:
  circle w0.025: c113.495,138.083 r1.25
  circle w0.025: c113.512,115.196 r1.25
